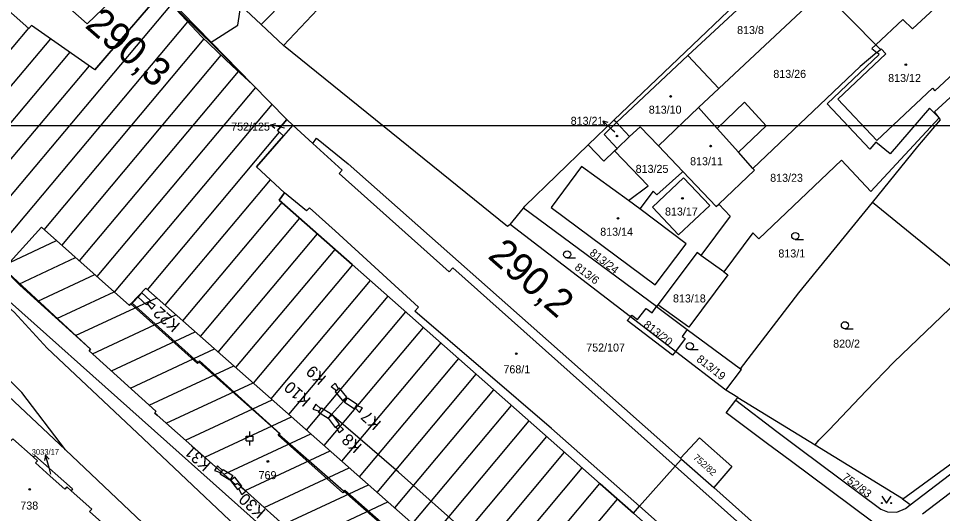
# Model space of a CAD drawing. Extents: x -496682 to -495776, y -1088797 to -1088018.
# Drawn here: x -496499.5 to -496303.3, y -1088246.6 to -1088141.5 of the extents above; entities that cross this region are included whole.
import ezdxf

# ---------------------------------------------------------------- set-up
doc = ezdxf.new("R2010")
doc.units = 0
for name, color, linetype in [('_PS01_CCTV', 7, 'Continuous'), ('Default', 7, 'Continuous'), ('Hranice parcel', 7, 'Continuous'), ('Parcelní čísla', 7, 'Continuous'), ('Pop  PČ popisy', 7, 'Continuous'), ('Vnitřní kresba', 7, 'Continuous'), ('Vrstva 20', 7, 'Continuous'), ('Vrstva 54', 7, 'Continuous'), ('Vrstva 63', 7, 'Continuous'), ('Vrstva 7', 7, 'Continuous'), ('Značky budov', 7, 'Continuous'), ('Značky kultur', 7, 'Continuous')]:
    doc.layers.add(name, color=color, linetype=linetype)

# ---------------------------------------------------------------- blocks, each defined once
blk = doc.blocks.new('Kamera')
at = {"layer": 'Default'}
blk.add_lwpolyline([(0.0025, -0.00018), (0.0001, -0.00058), (-0.0001, 0.00058), (0.0023, 0.00098)], close=True, dxfattribs=at)
blk.add_lwpolyline([(0.00245, 0.00011), (0.00389, 0.00005), (0.0037, 0.00121), (0.00236, 0.00065)], dxfattribs=at)

msp = doc.modelspace()

# ---------------------------------------------------------------- linework, layer by layer
at = {"layer": '_PS01_CCTV'}
for p, q in [((-496475.34, -1088202.01), (-496473.7, -1088200.27)), ((-496461.34, -1088214.57), (-496475.34, -1088202.01)), ((-496461.04, -1088214.23), (-496461.34, -1088214.57)), ((-496443.89, -1088229.74), (-496461.04, -1088214.23)), ((-496433.01, -1088225.61), (-496429.82, -1088222.06)), ((-496418.78, -1088237.87), (-496433.01, -1088225.61)), ((-496444.06, -1088229.98), (-496443.89, -1088229.74)), ((-496430.45, -1088241.91), (-496444.06, -1088229.98)), ((-496398.58, -1088255.79), (-496418.78, -1088237.87)), ((-496430.19, -1088241.73), (-496430.45, -1088241.91)), ((-496412.45, -1088257.3), (-496430.19, -1088241.73))]:
    msp.add_line(p, q, dxfattribs=at)
at = {"layer": 'Hranice parcel'}
for p, q in [((-496373.06, -1088163.12), (-496321.41, -1088113.75)), ((-496419.93, -1088122.62), (-496443.22, -1088147.27)), ((-496333.69, -1088127.43), (-496357.36, -1088149.42)), ((-496473.26, -1088131.47), (-496458.59, -1088146.6)), ((-496350.76, -1088156.43), (-496328.71, -1088135.71)), ((-496328.71, -1088135.71), (-496317.45, -1088147.13)), ((-496447.95, -1088142.83), (-496452.25, -1088138.8)), ((-496443.22, -1088147.27), (-496447.95, -1088142.83)), ((-496458.59, -1088146.6), (-496449.81, -1088155.53)), ((-496317.45, -1088147.13), (-496316.44, -1088148.1)), ((-496357.36, -1088149.42), (-496372.55, -1088163.66)), ((-496357.36, -1088149.42), (-496350.76, -1088156.43)), ((-496317.24, -1088148.77), (-496316.44, -1088148.1)), ((-496442.49, -1088162.96), (-496449.81, -1088155.53)), ((-496355.12, -1088160.45), (-496350.76, -1088156.43)), ((-496363.63, -1088168.58), (-496355.12, -1088160.45)), ((-496442.49, -1088162.96), (-496441.25, -1088164.22)), ((-496372.55, -1088163.66), (-496373.06, -1088163.12)), ((-496441.25, -1088164.22), (-496443.2, -1088166.44)), ((-496372.55, -1088163.66), (-496369.75, -1088166.63)), ((-496448.94, -1088173.01), (-496443.2, -1088166.44)), ((-496372.37, -1088169.12), (-496369.75, -1088166.63)), ((-496363.63, -1088168.58), (-496358.44, -1088174.04)), ((-496367.58, -1088181.95), (-496369.94, -1088180.21)), ((-496296.45, -1088198.31), (-496318.2, -1088180.61)), ((-496395.1, -1088185.29), (-496392.28, -1088181.83)), ((-496364.03, -1088202.7), (-496392.28, -1088181.83)), ((-496369.57, -1088204.88), (-496395.1, -1088185.29)), ((-496349.76, -1088195.32), (-496354.58, -1088191.83)), ((-496363.73, -1088202.36), (-496364.03, -1088202.7)), ((-496364.03, -1088202.7), (-496357.48, -1088207.54)), ((-496360, -1088212.22), (-496369.57, -1088204.88)), ((-496357.48, -1088207.54), (-496346.16, -1088215.94)), ((-496349.3, -1088220.43), (-496360, -1088212.22)), ((-496346.76, -1088221.99), (-496349.3, -1088220.43)), ((-496347.19, -1088222.58), (-496346.76, -1088221.99)), ((-496346.76, -1088221.99), (-496330.37, -1088232.05)), ((-496437.1, -1088282.6), (-496489.52, -1088233.14)), ((-496358.69, -1088235.08), (-496358.91, -1088234.89)), ((-496358.69, -1088235.08), (-496351.85, -1088241.15)), ((-496351.85, -1088241.15), (-496332.38, -1088258.39)), ((-496310.18, -1088244.79), (-496311.81, -1088243.59))]:
    msp.add_line(p, q, dxfattribs=at)
for points in [[(-496559, -1088077.16), (-496484.87, -1088142.67), (-496473.26, -1088131.47)], [(-496449.81, -1088155.53), (-496454.1, -1088151.6), (-496460.56, -1088145.42), (-496469.27, -1088136.13), (-496476.41, -1088144.48), (-496483.29, -1088152.42), (-496496.71, -1088143.01), (-496497.27, -1088143.67), (-496509.81, -1088132.58), (-496512.72, -1088135.39), (-496534.24, -1088116.3), (-496558.95, -1088090.57), (-496566.25, -1088088.69), (-496568.44, -1088087.46), (-496570.32, -1088085.3), (-496571.02, -1088084.13)], [(-496447.95, -1088142.83), (-496426.52, -1088121), (-496435.61, -1088111.52)], [(-496317.45, -1088147.13), (-496311.72, -1088141.73), (-496309.67, -1088143.77), (-496301.22, -1088135.9), (-496299.6, -1088137.62)], [(-496316.44, -1088148.1), (-496316.33, -1088148), (-496315.31, -1088149.08), (-496325.51, -1088158.67), (-496317.28, -1088167.48), (-496305.43, -1088156.36), (-496304.95, -1088156.9), (-496300.93, -1088153.13), (-496301.44, -1088152.61), (-496292.98, -1088144.67), (-496299.6, -1088137.62)], [(-496458.59, -1088146.6), (-496452.94, -1088142.96), (-496452.25, -1088138.8)], [(-496395.1, -1088185.29), (-496395.64, -1088185.72), (-496443.22, -1088147.27)], [(-496317.24, -1088148.77), (-496320.78, -1088151.75), (-496343.54, -1088173.37)], [(-496304.04, -1088162.67), (-496306.05, -1088160.58), (-496314.41, -1088170.29), (-496317.47, -1088167.8), (-496318.76, -1088169.3), (-496327.78, -1088159.67), (-496316.73, -1088149.19), (-496317.24, -1088148.77)], [(-496304.04, -1088162.67), (-496305.02, -1088161.37), (-496298.45, -1088155.33)], [(-496343.54, -1088173.37), (-496346.64, -1088169.91), (-496340.77, -1088164.33), (-496345.36, -1088159.28), (-496351.12, -1088164.91), (-496355.12, -1088160.45)], [(-496535.94, -1088160.08), (-496533.17, -1088166.28), (-496528.64, -1088174.22), (-496508.14, -1088199.6), (-496506.98, -1088200.58), (-496503.63, -1088201.84), (-496501.59, -1088202.85), (-496500.38, -1088203.92), (-496493.36, -1088211.52), (-496474.31, -1088229.54), (-496444.2, -1088257.99), (-496416.61, -1088284.03), (-496413.37, -1088286.95)], [(-496413.37, -1088286.95), (-496422.7, -1088272.51), (-496424.74, -1088270.02), (-496501.36, -1088201.6), (-496504.67, -1088198.35), (-496506.73, -1088196.1), (-496535.94, -1088160.08)], [(-496443.2, -1088166.44), (-496444.47, -1088165.33), (-496442.49, -1088162.96)], [(-496392.28, -1088181.83), (-496391.98, -1088181.42), (-496378.53, -1088168.35), (-496373.06, -1088163.12)], [(-496304.04, -1088162.67), (-496318.49, -1088178.29), (-496324.77, -1088171.65), (-496342.29, -1088188.3), (-496343.55, -1088187.04), (-496349.76, -1088195.32)], [(-496318.2, -1088180.61), (-496308.55, -1088168.74), (-496303.76, -1088163.03), (-496304.04, -1088162.67)], [(-496441.25, -1088164.22), (-496436.96, -1088168.06), (-496436.18, -1088166.94)], [(-496372.55, -1088163.66), (-496375.14, -1088166.17), (-496372.37, -1088169.12)], [(-496369.75, -1088166.63), (-496367.5, -1088164.53), (-496363.63, -1088168.58)], [(-496436.18, -1088166.94), (-496429.51, -1088172.39), (-496378.3, -1088217.72), (-496358.91, -1088234.89)], [(-496369.94, -1088180.21), (-496365.78, -1088177.09), (-496372.95, -1088169.67), (-496372.37, -1088169.12)], [(-496444.11, -1088180.1), (-496442.99, -1088178.56), (-496448.94, -1088173.01)], [(-496369.94, -1088180.21), (-496379.95, -1088172.96), (-496386.4, -1088181.69), (-496364.31, -1088198.06), (-496357.74, -1088189.38), (-496367.58, -1088181.95)], [(-496358.44, -1088174.04), (-496358.66, -1088174.24), (-496363.93, -1088178.99), (-496364.72, -1088178.18), (-496367.58, -1088181.95)], [(-496358.44, -1088174.04), (-496351.36, -1088181.47), (-496350.8, -1088180.95)], [(-496350.8, -1088180.95), (-496343.21, -1088173.74), (-496343.54, -1088173.37)], [(-496358.3, -1088175.34), (-496364.87, -1088181.6), (-496359.32, -1088187.51), (-496352.73, -1088181.25), (-496358.3, -1088175.34)], [(-496368.91, -1088246.59), (-496375.97, -1088240.32), (-496428.63, -1088193.79), (-496444.11, -1088180.1)], [(-496350.8, -1088180.95), (-496348.4, -1088183.52), (-496354.58, -1088191.83)], [(-496346.16, -1088215.94), (-496333.82, -1088199.82), (-496318.2, -1088180.61)], [(-496502.56, -1088194.71), (-496494.62, -1088185.88), (-496475.92, -1088202.47), (-496475.59, -1088202.1), (-496472.44, -1088198.82), (-496390.14, -1088271.47), (-496393.43, -1088275.14), (-496397.84, -1088280.09)], [(-496354.58, -1088191.83), (-496355.42, -1088191.22), (-496363.73, -1088202.36)], [(-496502.56, -1088194.71), (-496499.18, -1088198.14), (-496484.17, -1088211.77), (-496484.46, -1088212.1)], [(-496311.81, -1088243.59), (-496254.42, -1088201.7), (-496253.97, -1088194.3)], [(-496349.76, -1088195.32), (-496348.88, -1088195.96), (-496357.15, -1088207.11), (-496363.73, -1088202.36)], [(-496330.37, -1088232.05), (-496329.58, -1088231.08), (-496327.35, -1088228.88), (-496319.53, -1088220.58), (-496313.61, -1088214.48), (-496300.1, -1088201.57), (-496296.45, -1088198.31)], [(-496310.18, -1088244.79), (-496257.12, -1088204.31), (-496254.49, -1088202.87), (-496251.61, -1088202), (-496250.98, -1088201.92)], [(-496369.57, -1088204.88), (-496369.28, -1088204.51), (-496368.03, -1088205.43), (-496366.23, -1088203.15), (-496364.97, -1088204.01), (-496364.03, -1088202.7)], [(-496489.52, -1088233.14), (-496498.76, -1088220.97), (-496513.88, -1088205.89)], [(-496307.55, -1088246.72), (-496254.8, -1088206.49), (-496251.12, -1088205.07), (-496249.48, -1088204.87)], [(-496357.48, -1088207.54), (-496358.57, -1088209.03), (-496357.92, -1088209.48), (-496360, -1088212.22)], [(-496484.46, -1088212.1), (-496470.35, -1088224.88), (-496470.54, -1088225.36), (-496470.06, -1088225.79), (-496453.4, -1088240.47), (-496453, -1088240.25), (-496439.57, -1088252.31), (-496439.57, -1088252.71), (-496422.32, -1088268.24), (-496421.99, -1088267.93), (-496402.24, -1088285.02)], [(-496349.3, -1088220.43), (-496345.96, -1088216.09), (-496346.16, -1088215.94)], [(-496489.52, -1088233.14), (-496501.62, -1088221.73), (-496503.75, -1088220.19), (-496505.29, -1088219.82), (-496506.99, -1088220.08), (-496508.76, -1088221.17), (-496510.2, -1088222.61)], [(-496496.39, -1088234.62), (-496500.69, -1088230.76), (-496501.09, -1088231.2), (-496504.33, -1088228.29), (-496508.95, -1088224.15)], [(-496313.9, -1088251.57), (-496335.64, -1088235.39), (-496340.47, -1088231.82), (-496349.2, -1088225.23), (-496347.19, -1088222.58)], [(-496347.19, -1088222.58), (-496338.46, -1088229.24), (-496333.64, -1088232.87), (-496316.4, -1088245.74), (-496315, -1088246.3), (-496313.02, -1088246.35), (-496311.19, -1088245.56), (-496310.18, -1088244.79)], [(-496358.91, -1088234.89), (-496354.93, -1088230.54), (-496348.01, -1088236.66), (-496351.85, -1088241.15)], [(-496330.37, -1088232.05), (-496312.02, -1088243.31), (-496311.81, -1088243.59)], [(-496496.39, -1088234.62), (-496496.01, -1088234.31), (-496488.03, -1088241.42), (-496488.28, -1088241.81)], [(-496488.28, -1088241.81), (-496489.2, -1088240.98), (-496489.65, -1088241.47), (-496492.73, -1088238.72), (-496495.87, -1088235.9), (-496495.47, -1088235.45), (-496496.39, -1088234.62)], [(-496368.91, -1088246.59), (-496367.6, -1088245.11), (-496360.03, -1088236.59), (-496358.69, -1088235.08)], [(-496477.59, -1088252.18), (-496481.16, -1088249.12), (-496484.37, -1088246.23), (-496483.93, -1088245.73), (-496488.28, -1088241.81)], [(-496332.38, -1088258.39), (-496333.89, -1088259.9), (-496341.4, -1088268.22), (-496342.71, -1088269.83), (-496368.91, -1088246.59)]]:
    msp.add_lwpolyline(points, dxfattribs=at)
at = {"layer": 'Pop  PČ popisy'}
for p, q in [((-496373.26, -1088165.34), (-496375.42, -1088163.26)), ((-496375.42, -1088163.26), (-496374.35, -1088163.59)), ((-496375.42, -1088163.26), (-496375.05, -1088164.31)), ((-496445.91, -1088164.09), (-496444.82, -1088163.85)), ((-496443, -1088164.82), (-496445.91, -1088164.09)), ((-496445.91, -1088164.09), (-496445.06, -1088164.82)), ((-496372.87, -1088165.71), (-496373.26, -1088165.34)), ((-496493.75, -1088234.27), (-496493.95, -1088235.38)), ((-496492.92, -1088237.16), (-496493.75, -1088234.27)), ((-496493.75, -1088234.27), (-496492.99, -1088235.1)), ((-496492.59, -1088238.29), (-496492.92, -1088237.16))]:
    msp.add_line(p, q, dxfattribs=at)
at = {"layer": 'Vnitřní kresba'}
for p, q in [((-496317.45, -1088147.13), (-496318.3, -1088147.89)), ((-496318.3, -1088147.89), (-496317.24, -1088148.77)), ((-496351.12, -1088164.91), (-496346.64, -1088169.91)), ((-496436.96, -1088168.06), (-496430.78, -1088173.72)), ((-496375.24, -1088171.83), (-496378.53, -1088168.35)), ((-496372.95, -1088169.67), (-496375.24, -1088171.83)), ((-496430.78, -1088173.72), (-496431.39, -1088174.48)), ((-496431.39, -1088174.48), (-496408.05, -1088195.35)), ((-496438.32, -1088182.41), (-496442.99, -1088178.56)), ((-496437.69, -1088181.71), (-496438.32, -1088182.41)), ((-496432.27, -1088186.65), (-496437.69, -1088181.71)), ((-496414.52, -1088202.82), (-496432.27, -1088186.65)), ((-496408.05, -1088195.35), (-496407.27, -1088194.48)), ((-496360.03, -1088236.59), (-496407.27, -1088194.48)), ((-496461.46, -1088214.82), (-496475.59, -1088202.1)), ((-496415.31, -1088203.69), (-496414.52, -1088202.82)), ((-496386.33, -1088228.59), (-496415.31, -1088203.69)), ((-496370.22, -1088205.69), (-496369.57, -1088204.88)), ((-496360.6, -1088213.02), (-496370.22, -1088205.69)), ((-496360, -1088212.22), (-496360.6, -1088213.02)), ((-496461.15, -1088214.48), (-496461.46, -1088214.82)), ((-496444.06, -1088229.63), (-496461.15, -1088214.48)), ((-496444.32, -1088230.01), (-496444.06, -1088229.63)), ((-496430.62, -1088242.23), (-496444.32, -1088230.01)), ((-496386.33, -1088228.59), (-496367.6, -1088245.11)), ((-496360.03, -1088236.59), (-496333.89, -1088259.9)), ((-496430.31, -1088241.87), (-496430.62, -1088242.23)), ((-496430.31, -1088241.87), (-496412.66, -1088257.39)), ((-496367.6, -1088245.11), (-496341.4, -1088268.22))]:
    msp.add_line(p, q, dxfattribs=at)
at = {"layer": 'Vrstva 20'}
for p, q in [((-496503.34, -1088181.92), (-496466.96, -1088138.57)), ((-496511.49, -1088160.52), (-496497.3, -1088143.62)), ((-496504.95, -1088191.62), (-496463.52, -1088142.25)), ((-496508.23, -1088164.42), (-496492.64, -1088145.84)), ((-496494.03, -1088186.39), (-496460.05, -1088145.89)), ((-496504.97, -1088168.31), (-496488.53, -1088148.72)), ((-496490.29, -1088189.71), (-496456.43, -1088149.35)), ((-496501.71, -1088172.21), (-496484.42, -1088151.6)), ((-496486.54, -1088193.02), (-496452.78, -1088152.79)), ((-496482.8, -1088196.34), (-496449.12, -1088156.21)), ((-496479.06, -1088199.66), (-496445.6, -1088159.78)), ((-496472.08, -1088199.12), (-496444.03, -1088165.69)), ((-496468.33, -1088202.43), (-496445.96, -1088175.77)), ((-496464.58, -1088205.74), (-496443.5, -1088180.62)), ((-496460.83, -1088209.05), (-496439.75, -1088183.93)), ((-496501.33, -1088193.32), (-496491.42, -1088188.7)), ((-496457.08, -1088212.36), (-496436.01, -1088187.25)), ((-496453.33, -1088215.67), (-496432.26, -1088190.56)), ((-496499.37, -1088197.92), (-496487.34, -1088192.32)), ((-496449.58, -1088218.98), (-496428.51, -1088193.87)), ((-496495.37, -1088201.58), (-496483.27, -1088195.93)), ((-496445.83, -1088222.29), (-496424.76, -1088197.19)), ((-496491.36, -1088205.22), (-496479.19, -1088199.55)), ((-496442.08, -1088225.6), (-496421.02, -1088200.5)), ((-496487.35, -1088208.87), (-496470.13, -1088200.84)), ((-496483.76, -1088212.71), (-496466.04, -1088204.45)), ((-496438.33, -1088228.91), (-496417.27, -1088203.81)), ((-496479.74, -1088216.35), (-496461.95, -1088208.06)), ((-496434.58, -1088232.22), (-496413.52, -1088207.12)), ((-496430.83, -1088235.53), (-496409.77, -1088210.43)), ((-496475.72, -1088220), (-496457.86, -1088211.67)), ((-496427.08, -1088238.84), (-496406.02, -1088213.74)), ((-496471.7, -1088223.64), (-496453.77, -1088215.28)), ((-496423.33, -1088242.15), (-496402.28, -1088217.06)), ((-496468.12, -1088227.48), (-496449.68, -1088218.89)), ((-496419.58, -1088245.46), (-496398.53, -1088220.37)), ((-496464.02, -1088231.09), (-496445.59, -1088222.5)), ((-496415.83, -1088248.77), (-496394.78, -1088223.68)), ((-496459.93, -1088234.7), (-496441.5, -1088226.11)), ((-496412.08, -1088252.08), (-496391.03, -1088226.99)), ((-496455.83, -1088238.31), (-496437.41, -1088229.72)), ((-496408.33, -1088255.39), (-496387.28, -1088230.3)), ((-496451.33, -1088241.73), (-496433.33, -1088233.33)), ((-496404.58, -1088258.7), (-496383.54, -1088233.62)), ((-496447.29, -1088245.36), (-496429.24, -1088236.94)), ((-496400.83, -1088262.01), (-496379.79, -1088236.93)), ((-496443.25, -1088248.99), (-496425.15, -1088240.55)), ((-496397.08, -1088265.32), (-496376.04, -1088240.24)), ((-496393.34, -1088268.63), (-496372.3, -1088243.56)), ((-496439.5, -1088252.76), (-496421.06, -1088244.16))]:
    msp.add_line(p, q, dxfattribs=at)
at = {"layer": 'Vrstva 54'}
for points in [[(-496483.29, -1088152.42), (-496469.27, -1088136.13), (-496449.81, -1088155.53), (-496442.49, -1088162.96), (-496444.47, -1088165.33), (-496443.2, -1088166.44), (-496448.94, -1088173.01), (-496442.99, -1088178.56), (-496444.11, -1088180.1), (-496428.63, -1088193.79), (-496375.97, -1088240.32), (-496368.91, -1088246.59), (-496342.71, -1088269.83), (-496341.4, -1088268.22), (-496333.89, -1088259.9), (-496332.38, -1088258.39), (-496325.94, -1088264.24), (-496332.44, -1088271.21), (-496324.32, -1088278.18), (-496327.63, -1088281.05), (-496295.37, -1088310.06)], [(-496439.57, -1088252.31), (-496453, -1088240.25), (-496453.4, -1088240.47), (-496470.06, -1088225.79), (-496470.54, -1088225.36), (-496470.35, -1088224.88), (-496484.46, -1088212.1), (-496484.17, -1088211.77), (-496502.56, -1088194.71)]]:
    msp.add_lwpolyline(points, dxfattribs=at)
at = {"layer": 'Vrstva 63'}
msp.add_lwpolyline([(-496137.35, -1088164.24), (-496137.35, -1088461.24), (-496557.35, -1088461.24), (-496557.35, -1088164.24)], close=True, dxfattribs=at)
at = {"layer": 'Značky budov'}
for centre in [(-496311.09, -1088151.35), (-496361.02, -1088158.1), (-496372.4, -1088166.5), (-496352.53, -1088168.64), (-496358.51, -1088179.71), (-496372.21, -1088183.99), (-496393.79, -1088212.71), (-496446.53, -1088235.58), (-496497.1, -1088241.51)]:
    msp.add_circle(centre, 0.175, dxfattribs=at)
at = {"layer": 'Značky kultur'}
for p, q in [((-496334.57, -1088188.46), (-496332.82, -1088188.46)), ((-496382.99, -1088192.39), (-496381.24, -1088192.39)), ((-496324.03, -1088207.42), (-496322.28, -1088207.42)), ((-496356.95, -1088211.85), (-496355.2, -1088211.85)), ((-496450.38, -1088230.22), (-496450.38, -1088229.22)), ((-496451.13, -1088230.22), (-496449.63, -1088230.22)), ((-496451.13, -1088231.22), (-496451.13, -1088230.22)), ((-496451.13, -1088231.22), (-496449.63, -1088231.22)), ((-496450.38, -1088232.22), (-496450.38, -1088231.22)), ((-496449.63, -1088231.22), (-496449.63, -1088230.22))]:
    msp.add_line(p, q, dxfattribs=at)
msp.add_lwpolyline([(-496316.17, -1088242.93), (-496315.17, -1088244.43), (-496314.17, -1088242.93)], dxfattribs=at)
for centre, radius in [((-496334.57, -1088187.71), 0.75), ((-496382.99, -1088191.64), 0.75), ((-496324.03, -1088206.67), 0.75), ((-496356.95, -1088211.1), 0.75), ((-496316.17, -1088244.43), 0.1), ((-496314.17, -1088244.43), 0.1)]:
    msp.add_circle(centre, radius, dxfattribs=at)

# ---------------------------------------------------------------- block references
at = {"layer": '_PS01_CCTV'}
for p, xscale, yscale, rotation in [((-496473.68, -1088200.24), 1000, 999.9999999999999, -51.91171710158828), ((-496430.21, -1088222.3), 1000, -1000, 139.146394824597), ((-496429.93, -1088222.55), 1000, 1000.0000000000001, -43.63407174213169), ((-496433.39, -1088225.97), 1000.0000000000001, 1000.0000000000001, 138.95933911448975), ((-496433.27, -1088226.07), 1000, -1000, -43.4470160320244), ((-496454.27, -1088239.07), 1000.0000000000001, 999.9999999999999, 138.43890000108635), ((-496454.02, -1088239.29), 1000, -1000, -41.5610999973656)]:
    msp.add_blockref('Kamera', p, dxfattribs=dict(at, xscale=xscale, yscale=yscale, rotation=rotation))

# ---------------------------------------------------------------- texts
for s, p in [('K22', (-496464.98, -1088206.48)), ('K9', (-496433.94, -1088217.69)), ('K10', (-496437.21, -1088222.32)), ('K7', (-496422.28, -1088227.28)), ('K8', (-496426.38, -1088232.17)), ('K31', (-496458.36, -1088236)), ('K30', (-496446.84, -1088246.05))]:
    msp.add_text(s, height=2.5, rotation=138.43, dxfattribs=at).set_placement(p)
at = {"layer": 'Parcelní čísla'}
for s, height, p in [('813/8', 1.7, (-496346.91, -1088144.85)), ('813/26', 1.7, (-496339.22, -1088154.16)), ('813/12', 1.7, (-496314.84, -1088155.03)), ('813/10', 1.7, (-496365.66, -1088161.75)), ('813/21', 1.7, (-496382.24, -1088164.12)), ('752/125', 1.7, (-496454.32, -1088165.35)), ('813/11', 1.7, (-496356.89, -1088172.7)), ('813/25', 1.7, (-496368.45, -1088174.32)), ('813/23', 1.7, (-496339.89, -1088176.22)), ('813/17', 1.7, (-496362.22, -1088183.38)), ('813/14', 1.7, (-496375.97, -1088187.67)), ('813/1', 1.7, (-496338.15, -1088192.28)), ('813/18', 1.7, (-496360.52, -1088201.83)), ('752/107', 1.7, (-496378.94, -1088212.25)), ('820/2', 1.7, (-496326.52, -1088211.42)), ('768/1', 1.7, (-496396.52, -1088216.87)), ('3033/17', 1.2, (-496496.67, -1088234.16)), ('769', 1.7, (-496448.5, -1088239.34)), ('738', 1.7, (-496499.08, -1088245.8))]:
    msp.add_text(s, height=height, dxfattribs=at).set_placement(p)
for s, height, rotation, p in [('813/24', 1.7, 322, (-496378.37, -1088191.6)), ('813/6', 1.7, 323, (-496381.55, -1088194.68)), ('813/20', 1.7, 322, (-496366.92, -1088206.85)), ('813/19', 1.7, 322, (-496355.67, -1088214.17)), ('752/82', 1.4, 318, (-496356.33, -1088234.92)), ('752/83', 1.7, 323, (-496324.74, -1088239.23))]:
    msp.add_text(s, height=height, rotation=rotation, dxfattribs=at).set_placement(p)
at = {"layer": 'Vrstva 7'}
for s, p in [('290,3', (-496485.58, -1088143.27)), ('290,2', (-496400.07, -1088192.24))]:
    msp.add_text(s, height=6, rotation=318.9438, dxfattribs=at).set_placement(p)

doc.saveas('drawing.dxf')
